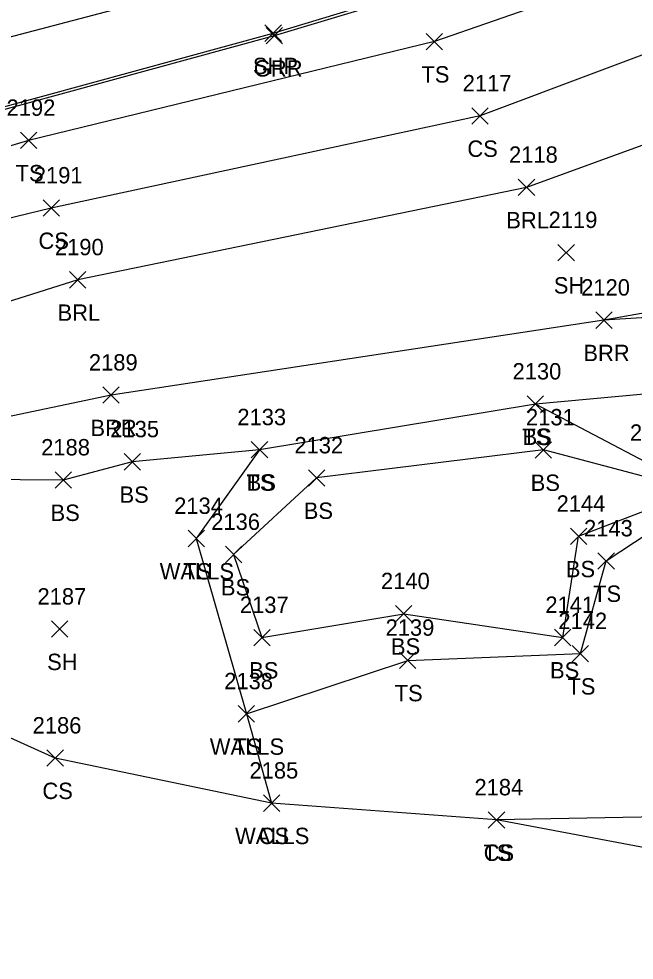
# Model space of a CAD drawing. Extents: x 1502194 to 1507887, y 142265 to 144150.
# Drawn here: x 1506653.1 to 1506728.1, y 143355.7 to 143470.6 of the extents above; entities that cross this region are included whole.
import ezdxf

# ---------------------------------------------------------------- set-up
doc = ezdxf.new("R2010")
doc.units = 0
for name, color, linetype in [('L_A', 7, 'Continuous'), ('L_I', 7, 'Continuous'), ('L_TIC', 7, 'Continuous'), ('LABL', 7, 'Continuous'), ('LELB', 7, 'Continuous'), ('LWS', 7, 'Continuous'), ('P_A', 7, 'Continuous'), ('P_TIC', 7, 'Continuous'), ('PET', 7, 'Continuous'), ('PSP', 7, 'Continuous'), ('R_A', 7, 'Continuous'), ('R_TIC', 7, 'Continuous'), ('RGR', 7, 'Continuous')]:
    doc.layers.add(name, color=color, linetype=linetype)

msp = doc.modelspace()

# ---------------------------------------------------------------- linework, layer by layer
at = {"layer": 'L_TIC'}
for points in [[(1506702.75, 143466.85), (1506704.75, 143468.85)], [(1506704.75, 143466.85), (1506702.75, 143468.85)], [(1506708.32, 143457.78), (1506710.32, 143459.78)], [(1506710.32, 143457.78), (1506708.32, 143459.78)], [(1506653.25, 143454.79), (1506655.25, 143456.79)], [(1506655.25, 143454.79), (1506653.25, 143456.79)], [(1506713.98, 143449.06), (1506715.98, 143451.06)], [(1506715.98, 143449.06), (1506713.98, 143451.06)], [(1506656.01, 143446.54), (1506658.01, 143448.54)], [(1506658.01, 143446.54), (1506656.01, 143448.54)], [(1506718.82, 143441.1), (1506720.82, 143443.1)], [(1506720.82, 143441.1), (1506718.82, 143443.1)], [(1506659.24, 143437.77), (1506661.24, 143439.77)], [(1506661.24, 143437.77), (1506659.24, 143439.77)], [(1506723.43, 143432.85), (1506725.43, 143434.85)], [(1506725.43, 143432.85), (1506723.43, 143434.85)], [(1506663.3, 143423.7), (1506665.3, 143425.7)], [(1506665.3, 143423.7), (1506663.3, 143425.7)], [(1506715.06, 143422.61), (1506717.06, 143424.61)], [(1506717.06, 143422.61), (1506715.06, 143424.61)], [(1506715.06, 143422.61), (1506717.06, 143424.61)], [(1506717.06, 143422.61), (1506715.06, 143424.61)], [(1506681.41, 143417.03), (1506683.41, 143419.03)], [(1506683.41, 143417.03), (1506681.41, 143419.03)], [(1506681.41, 143417.03), (1506683.41, 143419.03)], [(1506683.41, 143417.03), (1506681.41, 143419.03)], [(1506716.05, 143417.01), (1506718.05, 143419.01)], [(1506718.05, 143417.01), (1506716.05, 143419.01)], [(1506665.9, 143415.56), (1506667.9, 143417.56)], [(1506667.9, 143415.56), (1506665.9, 143417.56)], [(1506657.47, 143413.34), (1506659.47, 143415.34)], [(1506659.47, 143413.34), (1506657.47, 143415.34)], [(1506688.37, 143413.59), (1506690.37, 143415.59)], [(1506690.37, 143413.59), (1506688.37, 143415.59)], [(1506673.7, 143406.2), (1506675.7, 143408.2)], [(1506675.7, 143406.2), (1506673.7, 143408.2)], [(1506673.7, 143406.2), (1506675.7, 143408.2)], [(1506675.7, 143406.2), (1506673.7, 143408.2)], [(1506720.34, 143406.47), (1506722.34, 143408.47)], [(1506722.34, 143406.47), (1506720.34, 143408.47)], [(1506678.26, 143404.25), (1506680.26, 143406.25)], [(1506680.26, 143404.25), (1506678.26, 143406.25)], [(1506723.7, 143403.46), (1506725.7, 143405.46)], [(1506725.7, 143403.46), (1506723.7, 143405.46)], [(1506699.01, 143397.02), (1506701.01, 143399.02)], [(1506701.01, 143397.02), (1506699.01, 143399.02)], [(1506657.02, 143395.14), (1506659.02, 143397.14)], [(1506659.02, 143395.14), (1506657.02, 143397.14)], [(1506681.71, 143394.11), (1506683.71, 143396.11)], [(1506683.71, 143394.11), (1506681.71, 143396.11)], [(1506718.4, 143394.12), (1506720.4, 143396.12)], [(1506720.4, 143394.12), (1506718.4, 143396.12)], [(1506720.56, 143392.15), (1506722.56, 143394.15)], [(1506722.56, 143392.15), (1506720.56, 143394.15)], [(1506699.49, 143391.33), (1506701.49, 143393.33)], [(1506701.49, 143391.33), (1506699.49, 143393.33)], [(1506679.81, 143384.8), (1506681.81, 143386.8)], [(1506681.81, 143384.8), (1506679.81, 143386.8)], [(1506679.81, 143384.8), (1506681.81, 143386.8)], [(1506681.81, 143384.8), (1506679.81, 143386.8)], [(1506656.49, 143379.4), (1506658.49, 143381.4)], [(1506658.49, 143379.4), (1506656.49, 143381.4)], [(1506682.88, 143373.9), (1506684.88, 143375.9)], [(1506684.88, 143373.9), (1506682.88, 143375.9)], [(1506682.88, 143373.9), (1506684.88, 143375.9)], [(1506684.88, 143373.9), (1506682.88, 143375.9)], [(1506710.32, 143371.85), (1506712.32, 143373.85)], [(1506712.32, 143371.85), (1506710.32, 143373.85)], [(1506710.32, 143371.85), (1506712.32, 143373.85)], [(1506712.32, 143371.85), (1506710.32, 143373.85)]]:
    msp.add_lwpolyline(points, dxfattribs=at)
at = {"layer": 'LABL'}
for points in [[(1506925.15, 143533.52), (1506885.27, 143516.72), (1506839.01, 143491.82), (1506812.47, 143480.11), (1506797.79, 143478.92), (1506756.88, 143465.31), (1506714.98, 143450.06), (1506660.24, 143438.77), (1506613.3, 143423.94), (1506616.52, 143414.64)], [(1506850.82, 143464.05), (1506827.75, 143457.15), (1506806.24, 143448.63), (1506776.99, 143440.27), (1506769, 143436.63), (1506724.43, 143433.85), (1506664.3, 143424.7), (1506616.52, 143414.64)]]:
    msp.add_lwpolyline(points, dxfattribs=at)
at = {"layer": 'LELB'}
for points in [[(1506920.49, 143550.15), (1506879.81, 143532.73), (1506832.93, 143512.84), (1506791.89, 143498.35), (1506750.34, 143484.06), (1506703.75, 143467.85), (1506654.25, 143455.79), (1506605.88, 143441.31), (1506565.5, 143431.73), (1506554.53, 143418.24), (1506550.8, 143411.14), (1506553.36, 143401.15), (1506568.06, 143393.58), (1506589.98, 143377.59)], [(1506885.27, 143516.72), (1506836.36, 143503.21), (1506808.72, 143492.99), (1506794.07, 143487.49), (1506753.53, 143475.43), (1506709.32, 143458.78), (1506657.01, 143447.54), (1506608.42, 143435.74), (1506565.83, 143422.65), (1506556.41, 143414.68), (1506554.63, 143405.1), (1506570.25, 143400.38), (1506594.37, 143381.91)], [(1506771.28, 143442.14), (1506724.43, 143433.85)], [(1506771.18, 143428.84), (1506750.65, 143429.58), (1506732.88, 143425.16), (1506716.06, 143423.61)], [(1506773, 143420.81), (1506763.92, 143423.74), (1506751.84, 143425.09), (1506743.8, 143419.65), (1506731.79, 143414.11), (1506717.05, 143418.01), (1506689.37, 143414.59), (1506679.26, 143405.25), (1506682.71, 143395.11), (1506700.01, 143398.02), (1506719.4, 143395.12), (1506721.34, 143407.47), (1506733.32, 143412.08), (1506746.12, 143411.48), (1506755.01, 143409.7), (1506773.79, 143401.35), (1506783.19, 143400.63), (1506781.98, 143409.11), (1506785.56, 143413.5)], [(1506730.3, 143416.13), (1506716.06, 143423.61), (1506682.41, 143418.03), (1506674.7, 143407.2)], [(1506682.41, 143418.03), (1506666.9, 143416.56), (1506658.47, 143414.34), (1506616.52, 143414.64), (1506592.02, 143413.95), (1506569.09, 143412.31), (1506558.16, 143410.47)], [(1506821.73, 143363.41), (1506805.08, 143357), (1506771.29, 143358.16), (1506752.16, 143369.48), (1506733.38, 143373.29), (1506711.32, 143372.85), (1506683.88, 143374.9), (1506657.49, 143380.4), (1506618.98, 143397.77), (1506593.06, 143405.28), (1506569.34, 143407.78), (1506558.21, 143408.76), (1506558.16, 143410.47)], [(1506680.81, 143385.8), (1506700.49, 143392.33), (1506721.56, 143393.15), (1506724.7, 143404.46), (1506733.41, 143410.22), (1506745.22, 143408.74), (1506754.57, 143407.63), (1506773.81, 143399.34), (1506785.18, 143398.23), (1506783.59, 143408.91), (1506786.24, 143410.9), (1506795.32, 143401.84), (1506810.64, 143383.72), (1506813.18, 143377.58), (1506821.73, 143363.41)], [(1506762.91, 143355.73), (1506749.11, 143368.02), (1506730.95, 143369.17), (1506711.32, 143372.85)]]:
    msp.add_lwpolyline(points, dxfattribs=at)
at = {"layer": 'LWS'}
msp.add_lwpolyline([(1506674.7, 143407.2), (1506680.81, 143385.8), (1506683.88, 143374.9)], dxfattribs=at)
at = {"layer": 'P_TIC'}
for points in [[(1506683.08, 143467.88), (1506685.08, 143469.88)], [(1506685.08, 143467.88), (1506683.08, 143469.88)]]:
    msp.add_lwpolyline(points, dxfattribs=at)
at = {"layer": 'PET'}
msp.add_lwpolyline([(1506536.88, 143441.34), (1506584.71, 143452.38), (1506632.33, 143463.25), (1506682.2, 143476.4), (1506730.21, 143490.72), (1506780.44, 143507.94), (1506828.66, 143525.9), (1506867.29, 143541.82), (1506915.31, 143562.43)], dxfattribs=at)
at = {"layer": 'PSP'}
msp.add_lwpolyline([(1506542.57, 143434.01), (1506586.24, 143444.04), (1506633.16, 143454.96), (1506684.08, 143468.88), (1506730.5, 143482.95), (1506782.84, 143500.58), (1506831.22, 143518.57), (1506871.13, 143534.59), (1506917.52, 143554.61)], dxfattribs=at)
at = {"layer": 'R_TIC'}
for points in [[(1506683.23, 143467.58), (1506685.23, 143469.58)], [(1506685.23, 143467.58), (1506683.23, 143469.58)]]:
    msp.add_lwpolyline(points, dxfattribs=at)
at = {"layer": 'RGR'}
msp.add_lwpolyline([(1506543.48, 143429.76), (1506556.69, 143434.17), (1506568.66, 143438.23), (1506586.4, 143443.43), (1506633.04, 143454.6), (1506684.23, 143468.58), (1506730.71, 143482.6), (1506783.02, 143500.15), (1506831.56, 143518.03), (1506871.47, 143534.19), (1506917.7, 143554.27)], dxfattribs=at)

# ---------------------------------------------------------------- texts
at = {"layer": 'L_A'}
for s, p in [('TS', (1506702.16, 143462.85)), ('CS', (1506707.77, 143453.78)), ('TS', (1506652.66, 143450.79)), ('BRL', (1506712.52, 143445.06)), ('CS', (1506655.45, 143442.54)), ('SH', (1506718.31, 143437.1)), ('BRL', (1506657.78, 143433.77)), ('BRR', (1506721.92, 143428.85)), ('BRR', (1506661.79, 143419.7)), ('TS', (1506714.47, 143418.61)), ('BS', (1506714.5, 143418.61)), ('TS', (1506680.82, 143413.03)), ('BS', (1506680.85, 143413.03)), ('BS', (1506715.49, 143413.01)), ('BS', (1506665.34, 143411.56)), ('BS', (1506656.92, 143409.34)), ('BS', (1506687.81, 143409.59)), ('BS', (1506719.78, 143402.47)), ('WALLS', (1506670.24, 143402.2)), ('TS', (1506673.11, 143402.2)), ('BS', (1506677.7, 143400.25)), ('TS', (1506723.11, 143399.46)), ('BS', (1506698.45, 143393.02)), ('SH', (1506656.51, 143391.14)), ('BS', (1506681.15, 143390.11)), ('BS', (1506717.85, 143390.12)), ('TS', (1506719.97, 143388.15)), ('TS', (1506698.9, 143387.33)), ('WALLS', (1506676.35, 143380.8)), ('TS', (1506679.22, 143380.8)), ('CS', (1506655.93, 143375.4)), ('WALLS', (1506679.43, 143369.9)), ('CS', (1506682.32, 143369.9)), ('TS', (1506709.73, 143367.85)), ('CS', (1506709.76, 143367.85))]:
    msp.add_text(s, height=2, dxfattribs=at).set_placement(p)
at = {"layer": 'L_I'}
for s, p in [('2117', (1506707.2, 143461.78)), ('2192', (1506651.56, 143458.79)), ('2118', (1506712.85, 143453.06)), ('2191', (1506654.88, 143450.54)), ('2119', (1506717.68, 143445.1)), ('2190', (1506657.46, 143441.77)), ('2120', (1506721.65, 143436.85)), ('2189', (1506661.6, 143427.7)), ('2130', (1506713.28, 143426.61)), ('2130', (1506713.28, 143426.61)), ('2133', (1506679.71, 143421.03)), ('2133', (1506679.71, 143421.03)), ('2131', (1506714.92, 143421.01)), ('2135', (1506664.21, 143419.56)), ('2129', (1506727.6, 143419.13)), ('2188', (1506655.78, 143417.34)), ('2132', (1506686.67, 143417.59)), ('2144', (1506718.65, 143410.47)), ('2134', (1506672, 143410.2)), ('2134', (1506672, 143410.2)), ('2136', (1506676.52, 143408.25)), ('2143', (1506722, 143407.46)), ('2140', (1506697.23, 143401.02)), ('2187', (1506655.33, 143399.14)), ('2137', (1506680.02, 143398.11)), ('2141', (1506717.28, 143398.12)), ('2142', (1506718.87, 143396.15)), ('2139', (1506697.79, 143395.33)), ('2138', (1506678.11, 143388.8)), ('2138', (1506678.11, 143388.8)), ('2186', (1506654.74, 143383.4)), ('2185', (1506681.19, 143377.9)), ('2185', (1506681.19, 143377.9)), ('2184', (1506708.63, 143375.85)), ('2184', (1506708.63, 143375.85))]:
    msp.add_text(s, height=2, dxfattribs=at).set_placement(p)
at = {"layer": 'P_A'}
msp.add_text('SHP', height=2, dxfattribs=at).set_placement((1506681.61, 143463.88))
at = {"layer": 'R_A'}
msp.add_text('GRR', height=2, dxfattribs=at).set_placement((1506681.72, 143463.58))

doc.saveas('drawing.dxf')
